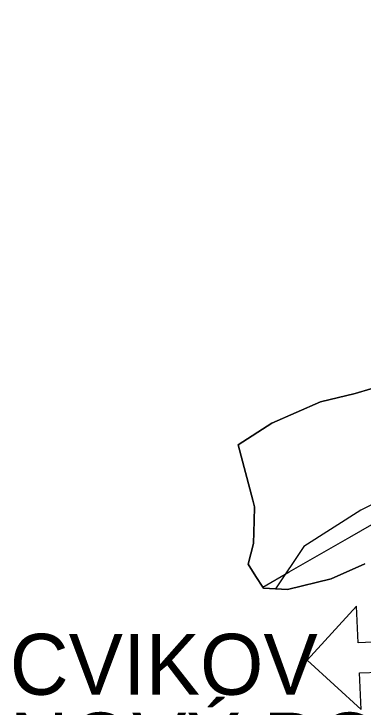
# Model space of a CAD drawing. Extents: x -706771 to -698463, y -971709 to -967107.
# Drawn here: x -706406 to -705977, y -969665 to -968812 of the extents above; entities that cross this region are included whole.
import ezdxf

# ---------------------------------------------------------------- set-up
doc = ezdxf.new("R2010")
doc.units = 0
for name, color, linetype in [('_KRAJINNY CELEK', 7, 'Continuous'), ('_KRAJINNY OKRSEK', 7, 'Continuous'), ('Hranice katastralnich uzemi', 7, 'Continuous'), ('Hranice řešeného území', 7, 'Continuous'), ('KN_Hranice_parcel', 7, 'Continuous'), ('Komunikace popis smery a sipky', 7, 'Continuous'), ('Trasy turistické S', 7, 'Continuous'), ('Typ krajiny běžné 5M2', 7, 'Continuous')]:
    doc.layers.add(name, color=color, linetype=linetype)

msp = doc.modelspace()

# ---------------------------------------------------------------- linework, layer by layer
at = {"layer": '_KRAJINNY CELEK'}
msp.add_lwpolyline([(-705967.15, -969273.31), (-705986.52, -969279.13), (-706029.04, -969289.6), (-706089.13, -969315.75), (-706130.47, -969342.46), (-706112.4, -969410.6), (-706110.23, -969418.8), (-706110.52, -969435.72), (-706111.35, -969463.76), (-706118.14, -969489.19), (-706108.51, -969504.38), (-706100.18, -969517.53), (-706099.33, -969518.86), (-706069.72, -969520.33), (-706015.8, -969507.23), (-705974.37, -969488.98)], dxfattribs=at)
at = {"layer": '_KRAJINNY OKRSEK'}
msp.add_lwpolyline([(-705967.15, -969273.31), (-705986.52, -969279.13), (-706029.04, -969289.6), (-706089.13, -969315.75), (-706130.47, -969342.46), (-706112.4, -969410.6), (-706110.23, -969418.8), (-706110.52, -969435.72), (-706111.35, -969463.76), (-706118.14, -969489.19), (-706108.51, -969504.38), (-706100.18, -969517.53), (-706099.33, -969518.86), (-706069.72, -969520.33), (-706015.8, -969507.23), (-705974.37, -969488.98)], dxfattribs=at)
at = {"layer": 'Hranice katastralnich uzemi'}
msp.add_lwpolyline([(-705967.15, -969273.31), (-705986.52, -969279.13), (-706029.04, -969289.6), (-706089.13, -969315.75), (-706130.47, -969342.46), (-706112.4, -969410.6), (-706110.23, -969418.8), (-706110.52, -969435.72), (-706111.35, -969463.76), (-706118.14, -969489.19), (-706108.51, -969504.38), (-706100.18, -969517.53), (-706099.33, -969518.86), (-706069.72, -969520.33), (-706015.8, -969507.23), (-705974.37, -969488.98)], dxfattribs=at)
at = {"layer": 'Hranice řešeného území'}
msp.add_lwpolyline([(-705974.37, -969488.98), (-706015.8, -969507.23), (-706069.72, -969520.33), (-706099.33, -969518.86), (-706100.18, -969517.53), (-706108.51, -969504.38), (-706118.14, -969489.19), (-706111.35, -969463.76), (-706110.52, -969435.72), (-706110.23, -969418.8), (-706112.4, -969410.6), (-706130.47, -969342.46), (-706089.13, -969315.75), (-706029.04, -969289.6), (-705986.52, -969279.13), (-705967.15, -969273.31)], dxfattribs=at)
at = {"layer": 'KN_Hranice_parcel'}
for p, q in [((-706118.14, -969489.19), (-706108.51, -969504.38)), ((-706015.8, -969507.23), (-705974.37, -969488.98)), ((-706108.51, -969504.38), (-706100.18, -969517.53)), ((-706100.18, -969517.53), (-706099.33, -969518.86))]:
    msp.add_line(p, q, dxfattribs=at)
for points in [[(-705924.54, -969285.82), (-705928.32, -969283.69), (-705943.44, -969274.25), (-705967.15, -969273.31), (-705986.52, -969279.13), (-706029.04, -969289.6), (-706089.13, -969315.75), (-706130.47, -969342.46), (-706112.4, -969410.6)], [(-706100.18, -969517.53), (-706067.68, -969498.62), (-705993.02, -969456.21), (-705938.93, -969424.87), (-705898.22, -969401.63), (-705863.11, -969381.74), (-705809.98, -969351.48)], [(-706112.4, -969410.6), (-706110.23, -969418.8), (-706110.52, -969435.72), (-706111.35, -969463.76), (-706118.14, -969489.19)], [(-706099.33, -969518.86), (-706069.72, -969520.33), (-706015.8, -969507.23)]]:
    msp.add_lwpolyline(points, dxfattribs=at)
at = {"layer": 'Komunikace popis smery a sipky'}
for p, q in [((-705984.83, -969541.06), (-706045.44, -969607.59)), ((-705982.73, -969586.01), (-705984.83, -969541.06)), ((-705937.78, -969583.91), (-705982.73, -969586.01)), ((-706045.44, -969607.59), (-705978.9, -969668.2)), ((-705981, -969623.25), (-705936.05, -969621.15)), ((-705978.9, -969668.2), (-705981, -969623.25))]:
    msp.add_line(p, q, dxfattribs=at)
at = {"layer": 'Trasy turistické S'}
msp.add_lwpolyline([(-705483.86, -968807.35), (-705500.29, -968822.06), (-705505.41, -968833.86), (-705520.26, -968868.98), (-705542.95, -968920.8), (-705563.94, -968967.94), (-705584.96, -969005.09), (-705590.72, -969037.61), (-705660.23, -969146.79), (-705683.33, -969183.03), (-705713.22, -969229.33), (-705767.94, -969298.65), (-705809.98, -969351.48), (-705917.95, -969393.87), (-705945.07, -969405.56), (-705979.64, -969422.9), (-706049.74, -969467.57), (-706084.53, -969519.6)], dxfattribs=at)
at = {"layer": 'Typ krajiny běžné 5M2'}
msp.add_lwpolyline([(-705967.15, -969273.31), (-705986.52, -969279.13), (-706029.04, -969289.6), (-706089.13, -969315.75), (-706130.47, -969342.46), (-706112.4, -969410.6), (-706110.23, -969418.8), (-706110.52, -969435.72), (-706111.35, -969463.76), (-706118.14, -969489.19), (-706108.51, -969504.38), (-706100.18, -969517.53), (-706099.33, -969518.86), (-706069.72, -969520.33), (-706015.8, -969507.23), (-705974.37, -969488.98)], dxfattribs=at)

# ---------------------------------------------------------------- texts
at = {"layer": 'Komunikace popis smery a sipky'}
for s, p in [('CVIKOV', (-706411.37, -969650.08)), ('NOVÝ BOR', (-706411.37, -969747.15))]:
    msp.add_text(s, height=75, dxfattribs=at).set_placement(p)

doc.saveas('drawing.dxf')
